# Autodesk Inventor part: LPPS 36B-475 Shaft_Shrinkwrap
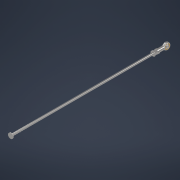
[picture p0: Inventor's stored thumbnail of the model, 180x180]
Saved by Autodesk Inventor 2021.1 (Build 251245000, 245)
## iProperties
Created: 2020-09
Part Number: LPPS 36B-475 Shaft_Shrinkwrap
Material: Generic
Document SubType Name: Modeling
Designer: J. Nielson
Density: 1 g/cm^3
Appearance: Default
Author: J. Nielson
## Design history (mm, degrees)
derived "LPPS 36B-475.iam"
body "Solid1"
node "LPPS-36B-475 ROD.ipt:1"
body "Solid2"
node "Custom Flanged Nut.ipt:1"
body "Solid3"
node "FEMALE Rod End SW.ipt:1"
body "Solid4"
node "JIS B 1181 - M8x1(4).ipt:1"
body "Solid5"
